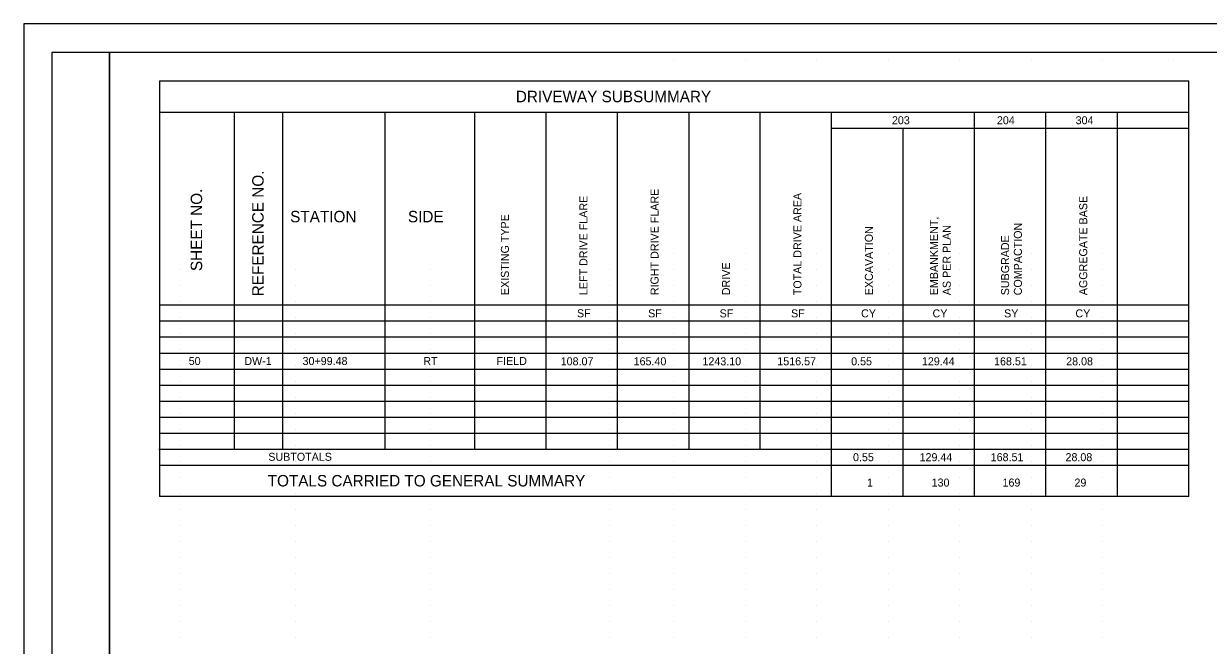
# Model space of a CAD drawing. Extents: x 2073163.9 to 2073197.9, y 634076.5 to 634098.5.
# Drawn here: x 2073163.95 to 2073184.67, y 634087.68 to 634098.55 of the extents above; entities that cross this region are included whole.
import ezdxf

# ---------------------------------------------------------------- set-up
doc = ezdxf.new("R2010")
doc.units = 0
for name, color, linetype in [('SH_Border', 7, 'Continuous'), ('SH_Cut_Line', 7, 'Continuous'), ('SH_Data', 7, 'Continuous'), ('SH_Text', 7, 'Continuous')]:
    doc.layers.add(name, color=color, linetype=linetype)

msp = doc.modelspace()

# ---------------------------------------------------------------- linework, layer by layer
at = {"layer": 'SH_Border'}
for p, q in [((2073166.321, 634097.55), (2073184.332, 634097.55)), ((2073166.321, 634097.55), (2073166.321, 634090.282)), ((2073184.331, 634090.282), (2073184.332, 634097.55)), ((2073184.331, 634090.282), (2073166.321, 634090.282))]:
    msp.add_line(p, q, dxfattribs=at)
for points in [[(2073164.446, 634098.05), (2073165.446, 634098.05), (2073165.446, 634077.05), (2073164.446, 634077.05)], [(2073165.446, 634098.05), (2073197.446, 634098.05), (2073197.446, 634077.05), (2073165.446, 634077.05)]]:
    msp.add_lwpolyline(points, close=True, dxfattribs=at)
at = {"layer": 'SH_Cut_Line'}
msp.add_lwpolyline([(2073163.946, 634076.55), (2073197.946, 634076.55), (2073197.946, 634098.55), (2073163.946, 634098.55)], close=True, dxfattribs=at)
at = {"layer": 'SH_Data'}
for p, q in [((2073175.321, 634097.91), (2073175.321, 634097.91)), ((2073176.571, 634097.91), (2073176.571, 634097.91)), ((2073177.821, 634097.91), (2073177.821, 634097.91)), ((2073179.071, 634097.91), (2073179.071, 634097.91)), ((2073180.321, 634097.91), (2073180.321, 634097.91)), ((2073181.571, 634097.91), (2073181.571, 634097.91)), ((2073181.571, 634097.91), (2073181.571, 634097.91)), ((2073182.821, 634097.91), (2073182.821, 634097.91)), ((2073182.821, 634097.91), (2073182.821, 634097.91)), ((2073182.821, 634097.91), (2073182.821, 634097.91)), ((2073184.071, 634097.91), (2073184.071, 634097.91)), ((2073184.071, 634097.91), (2073184.071, 634097.91)), ((2073184.071, 634097.91), (2073184.071, 634097.91)), ((2073184.071, 634097.91), (2073184.071, 634097.91)), ((2073166.323, 634097.002), (2073184.332, 634097.002)), ((2073167.635, 634091.11), (2073167.635, 634097.002)), ((2073168.48, 634091.11), (2073168.48, 634097.002)), ((2073170.27, 634091.11), (2073170.27, 634097.002)), ((2073171.836, 634091.11), (2073171.836, 634097.002)), ((2073173.086, 634091.11), (2073173.086, 634097.002)), ((2073174.336, 634091.11), (2073174.336, 634097.002)), ((2073175.586, 634091.11), (2073175.586, 634097.002)), ((2073176.831, 634091.11), (2073176.831, 634097.002)), ((2073178.081, 634090.282), (2073178.081, 634097.002)), ((2073180.581, 634090.282), (2073180.581, 634097.002)), ((2073181.831, 634090.282), (2073181.831, 634097.002)), ((2073181.831, 634090.282), (2073181.831, 634097.002)), ((2073183.081, 634090.282), (2073183.081, 634097.002)), ((2073178.073, 634096.722), (2073184.332, 634096.722)), ((2073179.331, 634090.282), (2073179.331, 634096.722)), ((2073175.321, 634094.538), (2073175.321, 634094.538)), ((2073176.571, 634094.538), (2073176.571, 634094.538)), ((2073177.821, 634094.538), (2073177.821, 634094.538)), ((2073179.071, 634094.538), (2073179.071, 634094.538)), ((2073180.321, 634094.538), (2073180.321, 634094.538)), ((2073181.571, 634094.538), (2073181.571, 634094.538)), ((2073181.571, 634094.538), (2073181.571, 634094.538)), ((2073182.821, 634094.538), (2073182.821, 634094.538)), ((2073182.821, 634094.538), (2073182.821, 634094.538)), ((2073182.821, 634094.538), (2073182.821, 634094.538)), ((2073184.071, 634094.538), (2073184.071, 634094.538)), ((2073184.071, 634094.538), (2073184.071, 634094.538)), ((2073184.071, 634094.538), (2073184.071, 634094.538)), ((2073184.071, 634094.538), (2073184.071, 634094.538)), ((2073165.821, 634094.258), (2073165.821, 634094.258)), ((2073166.696, 634094.258), (2073166.696, 634094.258)), ((2073168.696, 634094.258), (2073168.696, 634094.258)), ((2073171.071, 634094.258), (2073171.071, 634094.258)), ((2073172.821, 634094.258), (2073172.821, 634094.258)), ((2073174.196, 634094.258), (2073174.196, 634094.258)), ((2073175.321, 634094.258), (2073175.321, 634094.258)), ((2073176.571, 634094.258), (2073176.571, 634094.258)), ((2073177.821, 634094.258), (2073177.821, 634094.258)), ((2073179.071, 634094.258), (2073179.071, 634094.258)), ((2073180.321, 634094.258), (2073180.321, 634094.258)), ((2073181.571, 634094.258), (2073181.571, 634094.258)), ((2073182.821, 634094.258), (2073182.821, 634094.258)), ((2073184.071, 634094.258), (2073184.071, 634094.258)), ((2073165.821, 634093.978), (2073165.821, 634093.978)), ((2073166.696, 634093.978), (2073166.696, 634093.978)), ((2073168.696, 634093.978), (2073168.696, 634093.978)), ((2073171.071, 634093.978), (2073171.071, 634093.978)), ((2073172.821, 634093.978), (2073172.821, 634093.978)), ((2073174.196, 634093.978), (2073174.196, 634093.978)), ((2073175.321, 634093.978), (2073175.321, 634093.978)), ((2073176.571, 634093.978), (2073176.571, 634093.978)), ((2073177.821, 634093.978), (2073177.821, 634093.978)), ((2073179.071, 634093.978), (2073179.071, 634093.978)), ((2073180.321, 634093.978), (2073180.321, 634093.978)), ((2073181.571, 634093.978), (2073181.571, 634093.978)), ((2073182.821, 634093.978), (2073182.821, 634093.978)), ((2073184.071, 634093.978), (2073184.071, 634093.978)), ((2073165.821, 634093.698), (2073165.821, 634093.698)), ((2073166.321, 634093.63), (2073184.331, 634093.63)), ((2073166.696, 634093.698), (2073166.696, 634093.698)), ((2073168.696, 634093.698), (2073168.696, 634093.698)), ((2073171.071, 634093.698), (2073171.071, 634093.698)), ((2073172.821, 634093.698), (2073172.821, 634093.698)), ((2073173.078, 634093.63), (2073184.331, 634093.63)), ((2073174.196, 634093.698), (2073174.196, 634093.698)), ((2073175.321, 634093.698), (2073175.321, 634093.698)), ((2073176.571, 634093.698), (2073176.571, 634093.698)), ((2073177.821, 634093.698), (2073177.821, 634093.698)), ((2073179.071, 634093.698), (2073179.071, 634093.698)), ((2073180.321, 634093.698), (2073180.321, 634093.698)), ((2073181.571, 634093.698), (2073181.571, 634093.698)), ((2073182.821, 634093.698), (2073182.821, 634093.698)), ((2073184.071, 634093.698), (2073184.071, 634093.698)), ((2073165.821, 634093.418), (2073165.821, 634093.418)), ((2073166.323, 634093.35), (2073184.331, 634093.35)), ((2073166.696, 634093.418), (2073166.696, 634093.418)), ((2073168.696, 634093.418), (2073168.696, 634093.418)), ((2073171.071, 634093.418), (2073171.071, 634093.418)), ((2073172.821, 634093.418), (2073172.821, 634093.418)), ((2073174.196, 634093.418), (2073174.196, 634093.418)), ((2073175.321, 634093.418), (2073175.321, 634093.418)), ((2073176.571, 634093.418), (2073176.571, 634093.418)), ((2073177.821, 634093.418), (2073177.821, 634093.418)), ((2073179.071, 634093.418), (2073179.071, 634093.418)), ((2073180.321, 634093.418), (2073180.321, 634093.418)), ((2073181.571, 634093.418), (2073181.571, 634093.418)), ((2073182.821, 634093.418), (2073182.821, 634093.418)), ((2073184.071, 634093.418), (2073184.071, 634093.418)), ((2073165.821, 634093.138), (2073165.821, 634093.138)), ((2073166.696, 634093.138), (2073166.696, 634093.138)), ((2073168.696, 634093.138), (2073168.696, 634093.138)), ((2073171.071, 634093.138), (2073171.071, 634093.138)), ((2073172.821, 634093.138), (2073172.821, 634093.138)), ((2073174.196, 634093.138), (2073174.196, 634093.138)), ((2073175.321, 634093.138), (2073175.321, 634093.138)), ((2073176.571, 634093.138), (2073176.571, 634093.138)), ((2073177.821, 634093.138), (2073177.821, 634093.138)), ((2073179.071, 634093.138), (2073179.071, 634093.138)), ((2073180.321, 634093.138), (2073180.321, 634093.138)), ((2073181.571, 634093.138), (2073181.571, 634093.138)), ((2073182.821, 634093.138), (2073182.821, 634093.138)), ((2073184.071, 634093.138), (2073184.071, 634093.138)), ((2073166.331, 634093.07), (2073184.331, 634093.07)), ((2073165.821, 634092.858), (2073165.821, 634092.858)), ((2073166.327, 634092.79), (2073184.331, 634092.79)), ((2073166.696, 634092.858), (2073166.696, 634092.858)), ((2073168.696, 634092.858), (2073168.696, 634092.858)), ((2073171.071, 634092.858), (2073171.071, 634092.858)), ((2073172.821, 634092.858), (2073172.821, 634092.858)), ((2073174.196, 634092.858), (2073174.196, 634092.858)), ((2073175.321, 634092.858), (2073175.321, 634092.858)), ((2073176.571, 634092.858), (2073176.571, 634092.858)), ((2073177.821, 634092.858), (2073177.821, 634092.858)), ((2073179.071, 634092.858), (2073179.071, 634092.858)), ((2073180.321, 634092.858), (2073180.321, 634092.858)), ((2073181.571, 634092.858), (2073181.571, 634092.858)), ((2073182.821, 634092.858), (2073182.821, 634092.858)), ((2073184.071, 634092.858), (2073184.071, 634092.858)), ((2073165.821, 634092.578), (2073165.821, 634092.578)), ((2073166.324, 634092.51), (2073184.331, 634092.51)), ((2073166.696, 634092.578), (2073166.696, 634092.578)), ((2073168.696, 634092.578), (2073168.696, 634092.578)), ((2073171.071, 634092.578), (2073171.071, 634092.578)), ((2073172.821, 634092.578), (2073172.821, 634092.578)), ((2073174.196, 634092.578), (2073174.196, 634092.578)), ((2073175.321, 634092.578), (2073175.321, 634092.578)), ((2073176.571, 634092.578), (2073176.571, 634092.578)), ((2073177.821, 634092.578), (2073177.821, 634092.578)), ((2073179.071, 634092.578), (2073179.071, 634092.578)), ((2073180.321, 634092.578), (2073180.321, 634092.578)), ((2073181.571, 634092.578), (2073181.571, 634092.578)), ((2073182.821, 634092.578), (2073182.821, 634092.578)), ((2073184.071, 634092.578), (2073184.071, 634092.578)), ((2073165.821, 634092.298), (2073165.821, 634092.298)), ((2073166.696, 634092.298), (2073166.696, 634092.298)), ((2073168.696, 634092.298), (2073168.696, 634092.298)), ((2073171.071, 634092.298), (2073171.071, 634092.298)), ((2073172.821, 634092.298), (2073172.821, 634092.298)), ((2073174.196, 634092.298), (2073174.196, 634092.298)), ((2073175.321, 634092.298), (2073175.321, 634092.298)), ((2073176.571, 634092.298), (2073176.571, 634092.298)), ((2073177.821, 634092.298), (2073177.821, 634092.298)), ((2073179.071, 634092.298), (2073179.071, 634092.298)), ((2073180.321, 634092.298), (2073180.321, 634092.298)), ((2073181.571, 634092.298), (2073181.571, 634092.298)), ((2073182.821, 634092.298), (2073182.821, 634092.298)), ((2073184.071, 634092.298), (2073184.071, 634092.298)), ((2073166.321, 634092.23), (2073184.331, 634092.23)), ((2073165.821, 634092.018), (2073165.821, 634092.018)), ((2073166.318, 634091.95), (2073184.331, 634091.95)), ((2073166.696, 634092.018), (2073166.696, 634092.018)), ((2073168.696, 634092.018), (2073168.696, 634092.018)), ((2073171.071, 634092.018), (2073171.071, 634092.018)), ((2073172.821, 634092.018), (2073172.821, 634092.018)), ((2073174.196, 634092.018), (2073174.196, 634092.018)), ((2073175.321, 634092.018), (2073175.321, 634092.018)), ((2073176.571, 634092.018), (2073176.571, 634092.018)), ((2073177.821, 634092.018), (2073177.821, 634092.018)), ((2073179.071, 634092.018), (2073179.071, 634092.018)), ((2073180.321, 634092.018), (2073180.321, 634092.018)), ((2073181.571, 634092.018), (2073181.571, 634092.018)), ((2073182.821, 634092.018), (2073182.821, 634092.018)), ((2073184.071, 634092.018), (2073184.071, 634092.018)), ((2073165.821, 634091.738), (2073165.821, 634091.738)), ((2073166.316, 634091.67), (2073184.331, 634091.67)), ((2073166.696, 634091.738), (2073166.696, 634091.738)), ((2073168.696, 634091.738), (2073168.696, 634091.738)), ((2073171.071, 634091.738), (2073171.071, 634091.738)), ((2073172.821, 634091.738), (2073172.821, 634091.738)), ((2073174.196, 634091.738), (2073174.196, 634091.738)), ((2073175.321, 634091.738), (2073175.321, 634091.738)), ((2073176.571, 634091.738), (2073176.571, 634091.738)), ((2073177.821, 634091.738), (2073177.821, 634091.738)), ((2073179.071, 634091.738), (2073179.071, 634091.738)), ((2073180.321, 634091.738), (2073180.321, 634091.738)), ((2073181.571, 634091.738), (2073181.571, 634091.738)), ((2073182.821, 634091.738), (2073182.821, 634091.738)), ((2073184.071, 634091.738), (2073184.071, 634091.738)), ((2073165.821, 634091.458), (2073165.821, 634091.458)), ((2073166.696, 634091.458), (2073166.696, 634091.458)), ((2073168.696, 634091.458), (2073168.696, 634091.458)), ((2073171.071, 634091.458), (2073171.071, 634091.458)), ((2073172.821, 634091.458), (2073172.821, 634091.458)), ((2073174.196, 634091.458), (2073174.196, 634091.458)), ((2073175.321, 634091.458), (2073175.321, 634091.458)), ((2073176.571, 634091.458), (2073176.571, 634091.458)), ((2073177.821, 634091.458), (2073177.821, 634091.458)), ((2073179.071, 634091.458), (2073179.071, 634091.458)), ((2073180.321, 634091.458), (2073180.321, 634091.458)), ((2073181.571, 634091.458), (2073181.571, 634091.458)), ((2073182.821, 634091.458), (2073182.821, 634091.458)), ((2073184.071, 634091.458), (2073184.071, 634091.458)), ((2073166.313, 634091.39), (2073184.331, 634091.39)), ((2073165.821, 634091.178), (2073165.821, 634091.178)), ((2073166.31, 634091.11), (2073184.331, 634091.11)), ((2073166.696, 634091.178), (2073166.696, 634091.178)), ((2073168.696, 634091.178), (2073168.696, 634091.178)), ((2073171.071, 634091.178), (2073171.071, 634091.178)), ((2073172.821, 634091.178), (2073172.821, 634091.178)), ((2073174.196, 634091.178), (2073174.196, 634091.178)), ((2073175.321, 634091.178), (2073175.321, 634091.178)), ((2073176.571, 634091.178), (2073176.571, 634091.178)), ((2073177.821, 634091.178), (2073177.821, 634091.178)), ((2073179.071, 634091.178), (2073179.071, 634091.178)), ((2073180.321, 634091.178), (2073180.321, 634091.178)), ((2073181.571, 634091.178), (2073181.571, 634091.178)), ((2073182.821, 634091.178), (2073182.821, 634091.178)), ((2073184.071, 634091.178), (2073184.071, 634091.178)), ((2073165.821, 634090.898), (2073165.821, 634090.898)), ((2073166.331, 634090.83), (2073184.331, 634090.83)), ((2073166.696, 634090.898), (2073166.696, 634090.898)), ((2073168.696, 634090.898), (2073168.696, 634090.898)), ((2073171.071, 634090.898), (2073171.071, 634090.898)), ((2073172.821, 634090.898), (2073172.821, 634090.898)), ((2073174.196, 634090.898), (2073174.196, 634090.898)), ((2073175.321, 634090.898), (2073175.321, 634090.898)), ((2073176.571, 634090.898), (2073176.571, 634090.898)), ((2073177.821, 634090.898), (2073177.821, 634090.898)), ((2073179.071, 634090.898), (2073179.071, 634090.898)), ((2073180.321, 634090.898), (2073180.321, 634090.898)), ((2073181.571, 634090.898), (2073181.571, 634090.898)), ((2073182.821, 634090.898), (2073182.821, 634090.898)), ((2073184.071, 634090.898), (2073184.071, 634090.898)), ((2073165.821, 634090.618), (2073165.821, 634090.618)), ((2073166.696, 634090.618), (2073166.696, 634090.618)), ((2073168.696, 634090.618), (2073168.696, 634090.618)), ((2073171.071, 634090.618), (2073171.071, 634090.618)), ((2073172.821, 634090.618), (2073172.821, 634090.618)), ((2073174.196, 634090.618), (2073174.196, 634090.618)), ((2073175.321, 634090.618), (2073175.321, 634090.618)), ((2073176.571, 634090.618), (2073176.571, 634090.618)), ((2073177.821, 634090.618), (2073177.821, 634090.618)), ((2073179.071, 634090.618), (2073179.071, 634090.618)), ((2073180.321, 634090.618), (2073180.321, 634090.618)), ((2073181.571, 634090.618), (2073181.571, 634090.618)), ((2073182.821, 634090.618), (2073182.821, 634090.618)), ((2073184.071, 634090.618), (2073184.071, 634090.618)), ((2073165.821, 634090.338), (2073165.821, 634090.338)), ((2073166.696, 634090.338), (2073166.696, 634090.338)), ((2073168.696, 634090.338), (2073168.696, 634090.338)), ((2073171.071, 634090.338), (2073171.071, 634090.338)), ((2073172.821, 634090.338), (2073172.821, 634090.338)), ((2073174.196, 634090.338), (2073174.196, 634090.338)), ((2073175.321, 634090.338), (2073175.321, 634090.338)), ((2073176.571, 634090.338), (2073176.571, 634090.338)), ((2073177.821, 634090.338), (2073177.821, 634090.338)), ((2073179.071, 634090.338), (2073179.071, 634090.338)), ((2073180.321, 634090.338), (2073180.321, 634090.338)), ((2073181.571, 634090.338), (2073181.571, 634090.338)), ((2073182.821, 634090.338), (2073182.821, 634090.338)), ((2073184.071, 634090.338), (2073184.071, 634090.338)), ((2073165.821, 634090.058), (2073165.821, 634090.058)), ((2073166.696, 634090.058), (2073166.696, 634090.058)), ((2073168.696, 634090.058), (2073168.696, 634090.058)), ((2073171.071, 634090.058), (2073171.071, 634090.058)), ((2073172.821, 634090.058), (2073172.821, 634090.058)), ((2073174.196, 634090.058), (2073174.196, 634090.058)), ((2073175.321, 634090.058), (2073175.321, 634090.058)), ((2073176.571, 634090.058), (2073176.571, 634090.058)), ((2073177.821, 634090.058), (2073177.821, 634090.058)), ((2073179.071, 634090.058), (2073179.071, 634090.058)), ((2073180.321, 634090.058), (2073180.321, 634090.058)), ((2073181.571, 634090.058), (2073181.571, 634090.058)), ((2073182.821, 634090.058), (2073182.821, 634090.058)), ((2073184.071, 634090.058), (2073184.071, 634090.058)), ((2073165.821, 634089.778), (2073165.821, 634089.778)), ((2073166.696, 634089.778), (2073166.696, 634089.778)), ((2073168.696, 634089.778), (2073168.696, 634089.778)), ((2073171.071, 634089.778), (2073171.071, 634089.778)), ((2073172.821, 634089.778), (2073172.821, 634089.778)), ((2073174.196, 634089.778), (2073174.196, 634089.778)), ((2073175.321, 634089.778), (2073175.321, 634089.778)), ((2073176.571, 634089.778), (2073176.571, 634089.778)), ((2073177.821, 634089.778), (2073177.821, 634089.778)), ((2073179.071, 634089.778), (2073179.071, 634089.778)), ((2073180.321, 634089.778), (2073180.321, 634089.778)), ((2073181.571, 634089.778), (2073181.571, 634089.778)), ((2073182.821, 634089.778), (2073182.821, 634089.778)), ((2073184.071, 634089.778), (2073184.071, 634089.778)), ((2073165.821, 634089.498), (2073165.821, 634089.498)), ((2073166.696, 634089.498), (2073166.696, 634089.498)), ((2073168.696, 634089.498), (2073168.696, 634089.498)), ((2073171.071, 634089.498), (2073171.071, 634089.498)), ((2073172.821, 634089.498), (2073172.821, 634089.498)), ((2073174.196, 634089.498), (2073174.196, 634089.498)), ((2073175.321, 634089.498), (2073175.321, 634089.498)), ((2073176.571, 634089.498), (2073176.571, 634089.498)), ((2073177.821, 634089.498), (2073177.821, 634089.498)), ((2073179.071, 634089.498), (2073179.071, 634089.498)), ((2073180.321, 634089.498), (2073180.321, 634089.498)), ((2073181.571, 634089.498), (2073181.571, 634089.498)), ((2073182.821, 634089.498), (2073182.821, 634089.498)), ((2073184.071, 634089.498), (2073184.071, 634089.498)), ((2073165.821, 634089.218), (2073165.821, 634089.218)), ((2073166.696, 634089.218), (2073166.696, 634089.218)), ((2073168.696, 634089.218), (2073168.696, 634089.218)), ((2073171.071, 634089.218), (2073171.071, 634089.218)), ((2073172.821, 634089.218), (2073172.821, 634089.218)), ((2073174.196, 634089.218), (2073174.196, 634089.218)), ((2073175.321, 634089.218), (2073175.321, 634089.218)), ((2073176.571, 634089.218), (2073176.571, 634089.218)), ((2073177.821, 634089.218), (2073177.821, 634089.218)), ((2073179.071, 634089.218), (2073179.071, 634089.218)), ((2073180.321, 634089.218), (2073180.321, 634089.218)), ((2073181.571, 634089.218), (2073181.571, 634089.218)), ((2073182.821, 634089.218), (2073182.821, 634089.218)), ((2073184.071, 634089.218), (2073184.071, 634089.218)), ((2073165.821, 634088.938), (2073165.821, 634088.938)), ((2073166.696, 634088.938), (2073166.696, 634088.938)), ((2073168.696, 634088.938), (2073168.696, 634088.938)), ((2073171.071, 634088.938), (2073171.071, 634088.938)), ((2073172.821, 634088.938), (2073172.821, 634088.938)), ((2073174.196, 634088.938), (2073174.196, 634088.938)), ((2073175.321, 634088.938), (2073175.321, 634088.938)), ((2073176.571, 634088.938), (2073176.571, 634088.938)), ((2073177.821, 634088.938), (2073177.821, 634088.938)), ((2073179.071, 634088.938), (2073179.071, 634088.938)), ((2073180.321, 634088.938), (2073180.321, 634088.938)), ((2073181.571, 634088.938), (2073181.571, 634088.938)), ((2073182.821, 634088.938), (2073182.821, 634088.938)), ((2073184.071, 634088.938), (2073184.071, 634088.938)), ((2073165.821, 634088.658), (2073165.821, 634088.658)), ((2073166.696, 634088.658), (2073166.696, 634088.658)), ((2073168.696, 634088.658), (2073168.696, 634088.658)), ((2073171.071, 634088.658), (2073171.071, 634088.658)), ((2073172.821, 634088.658), (2073172.821, 634088.658)), ((2073174.196, 634088.658), (2073174.196, 634088.658)), ((2073175.321, 634088.658), (2073175.321, 634088.658)), ((2073176.571, 634088.658), (2073176.571, 634088.658)), ((2073177.821, 634088.658), (2073177.821, 634088.658)), ((2073179.071, 634088.658), (2073179.071, 634088.658)), ((2073180.321, 634088.658), (2073180.321, 634088.658)), ((2073181.571, 634088.658), (2073181.571, 634088.658)), ((2073182.821, 634088.658), (2073182.821, 634088.658)), ((2073184.071, 634088.658), (2073184.071, 634088.658)), ((2073165.821, 634088.378), (2073165.821, 634088.378)), ((2073166.696, 634088.378), (2073166.696, 634088.378)), ((2073168.696, 634088.378), (2073168.696, 634088.378)), ((2073171.071, 634088.378), (2073171.071, 634088.378)), ((2073172.821, 634088.378), (2073172.821, 634088.378)), ((2073174.196, 634088.378), (2073174.196, 634088.378)), ((2073175.321, 634088.378), (2073175.321, 634088.378)), ((2073176.571, 634088.378), (2073176.571, 634088.378)), ((2073177.821, 634088.378), (2073177.821, 634088.378)), ((2073179.071, 634088.378), (2073179.071, 634088.378)), ((2073180.321, 634088.378), (2073180.321, 634088.378)), ((2073181.571, 634088.378), (2073181.571, 634088.378)), ((2073182.821, 634088.378), (2073182.821, 634088.378)), ((2073184.071, 634088.378), (2073184.071, 634088.378)), ((2073165.821, 634088.098), (2073165.821, 634088.098)), ((2073166.696, 634088.098), (2073166.696, 634088.098)), ((2073168.696, 634088.098), (2073168.696, 634088.098)), ((2073171.071, 634088.098), (2073171.071, 634088.098)), ((2073172.821, 634088.098), (2073172.821, 634088.098)), ((2073174.196, 634088.098), (2073174.196, 634088.098)), ((2073175.321, 634088.098), (2073175.321, 634088.098)), ((2073176.571, 634088.098), (2073176.571, 634088.098)), ((2073177.821, 634088.098), (2073177.821, 634088.098)), ((2073179.071, 634088.098), (2073179.071, 634088.098)), ((2073180.321, 634088.098), (2073180.321, 634088.098)), ((2073181.571, 634088.098), (2073181.571, 634088.098)), ((2073182.821, 634088.098), (2073182.821, 634088.098)), ((2073184.071, 634088.098), (2073184.071, 634088.098)), ((2073165.821, 634087.818), (2073165.821, 634087.818)), ((2073166.696, 634087.818), (2073166.696, 634087.818)), ((2073168.696, 634087.818), (2073168.696, 634087.818)), ((2073171.071, 634087.818), (2073171.071, 634087.818)), ((2073172.821, 634087.818), (2073172.821, 634087.818)), ((2073174.196, 634087.818), (2073174.196, 634087.818)), ((2073175.321, 634087.818), (2073175.321, 634087.818)), ((2073176.571, 634087.818), (2073176.571, 634087.818)), ((2073177.821, 634087.818), (2073177.821, 634087.818)), ((2073179.071, 634087.818), (2073179.071, 634087.818)), ((2073180.321, 634087.818), (2073180.321, 634087.818)), ((2073181.571, 634087.818), (2073181.571, 634087.818)), ((2073182.821, 634087.818), (2073182.821, 634087.818)), ((2073184.071, 634087.818), (2073184.071, 634087.818))]:
    msp.add_line(p, q, dxfattribs=at)

# ---------------------------------------------------------------- texts
for s, p in [('DRIVEWAY SUBSUMMARY', (2073172.556, 634097.176)), ('STATION', (2073168.608, 634095.076)), ('SIDE', (2073170.668, 634095.076)), ('TOTALS CARRIED TO GENERAL SUMMARY', (2073168.215, 634090.456))]:
    msp.add_text(s, height=0.2, dxfattribs=at).set_placement(p)
for s, p in [('REFERENCE NO.', (2073168.144, 634093.782)), ('SHEET NO.', (2073167.068, 634094.223))]:
    msp.add_text(s, height=0.2, rotation=90, dxfattribs=at).set_placement(p)
at = {"layer": 'SH_Text'}
for s, rotation, p in [('203', 0.0001, (2073179.136, 634096.791)), ('204', 0.0001, (2073180.973, 634096.791)), ('304', 0.0001, (2073182.35, 634096.791)), ('RIGHT DRIVE FLARE', 90.0001, (2073175.053, 634093.801)), ('TOTAL DRIVE AREA', 90.0001, (2073177.553, 634093.801)), ('LEFT DRIVE FLARE', 90.0001, (2073173.808, 634093.803)), ('AGGREGATE BASE', 90.0001, (2073182.553, 634093.801)), ('EXISTING TYPE', 90.0001, (2073172.435, 634093.803)), ('EXCAVATION', 90.0001, (2073178.803, 634093.801)), ('EMBANKMENT,', 90.0001, (2073179.941, 634093.801)), ('AS PER PLAN', 90.0001, (2073180.165, 634093.801)), ('COMPACTION', 90.0001, (2073181.41, 634093.799)), ('SUBGRADE', 90.0001, (2073181.186, 634093.799)), ('DRIVE', 90.0001, (2073176.303, 634093.801)), ('SF', 0.0001, (2073173.626, 634093.415)), ('SF', 0.0001, (2073174.871, 634093.413)), ('SF', 0.0001, (2073176.121, 634093.413)), ('SF', 0.0001, (2073177.371, 634093.413)), ('CY', 0.0001, (2073178.597, 634093.413)), ('CY', 0.0001, (2073179.847, 634093.413)), ('SY', 0.0001, (2073181.099, 634093.413)), ('CY', 0.0001, (2073182.347, 634093.413)), ('50', 0.0001, (2073166.833, 634092.58)), ('DW-1', 0.0001, (2073167.806, 634092.58)), ('30+99.48', 0.0001, (2073168.825, 634092.58)), ('RT', 0.0001, (2073170.937, 634092.58)), ('FIELD', 0.0001, (2073172.219, 634092.58)), ('108.07', 0.0001, (2073173.341, 634092.575)), ('165.40', 0.0001, (2073174.617, 634092.575)), ('1243.10', 0.0001, (2073175.821, 634092.575)), ('1516.57', 0.0001, (2073177.131, 634092.575)), ('0.55', 0.0001, (2073178.423, 634092.575)), ('129.44', 0.0001, (2073179.661, 634092.575)), ('168.51', 0.0001, (2073180.923, 634092.575)), ('28.08', 0.0001, (2073182.185, 634092.575)), ('SUBTOTALS', 0.0001, (2073168.225, 634090.905)), ('0.55', 0.0001, (2073178.455, 634090.898)), ('129.44', 0.0001, (2073179.62, 634090.898)), ('168.51', 0.0001, (2073180.864, 634090.898)), ('28.08', 0.0001, (2073182.173, 634090.898)), ('1', 0.0001, (2073178.701, 634090.454)), ('130', 0.0001, (2073179.831, 634090.454)), ('169', 0.0001, (2073181.071, 634090.454)), ('29', 0.0001, (2073182.33, 634090.454))]:
    msp.add_text(s, height=0.14, rotation=rotation, dxfattribs=at).set_placement(p)

doc.saveas('drawing.dxf')
